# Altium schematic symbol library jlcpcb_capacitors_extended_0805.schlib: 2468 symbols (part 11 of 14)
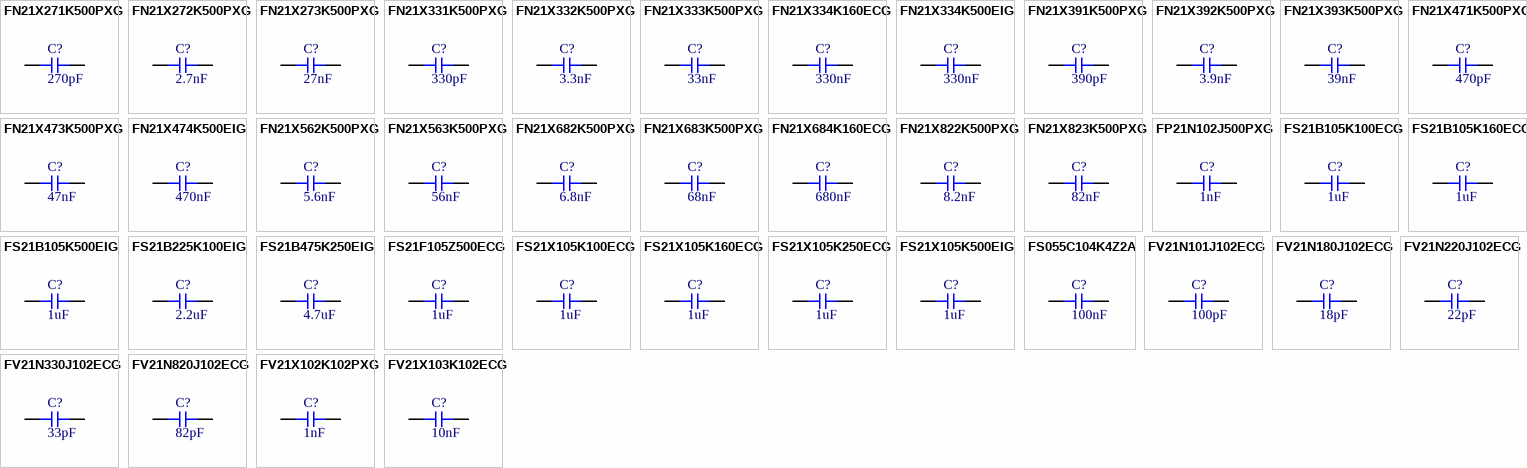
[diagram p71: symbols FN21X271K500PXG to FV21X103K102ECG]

## FS21X105K100ECG
designator C?  Capacitance: 1uF  (hidden comment: *)
Capacitor, Ceramic (MLCC), 1uF, ±10%, 10V, X7R, ±10%, SMD 0805; Manufacturer: PSA(Prosperity Dielectrics); Manufacturer Part Number: FS21X105K100ECG
footprint CAP-0805 (0805 (2012M) Capacitor)
pins: 1, 2

## FS21X105K160ECG
designator C?  Capacitance: 1uF  (hidden comment: *)
Capacitor, Ceramic (MLCC), 1uF, ±10%, 16V, X7R, ±10%, SMD 0805; Manufacturer: PSA(Prosperity Dielectrics); Manufacturer Part Number: FS21X105K160ECG
footprint CAP-0805 (0805 (2012M) Capacitor)
pins: 1, 2

## FS21X105K250ECG
designator C?  Capacitance: 1uF  (hidden comment: *)
Capacitor, Ceramic (MLCC), 1uF, ±10%, 25V, X7R, ±10%, SMD 0805; Manufacturer: PSA(Prosperity Dielectrics); Manufacturer Part Number: FS21X105K250ECG
footprint CAP-0805 (0805 (2012M) Capacitor)
pins: 1, 2

## FS21X105K500EIG
designator C?  Capacitance: 1uF  (hidden comment: *)
Capacitor, Ceramic (MLCC), 1uF, ±10%, 50V, X7R, ±10%, SMD 0805; Manufacturer: PSA(Prosperity Dielectrics); Manufacturer Part Number: FS21X105K500EIG
footprint CAP-0805 (0805 (2012M) Capacitor)
pins: 1, 2

## FS055C104K4Z2A
designator C?  Capacitance: 100nF  (hidden comment: *)
Capacitor, Ceramic (MLCC), 100nF, ±10%, 50V, X7R, ±10%, SMD 0805; Manufacturer: AVX; Manufacturer Part Number: FS055C104K4Z2A
footprint CAP-0805 (0805 (2012M) Capacitor)
pins: 1, 2

## FV21N101J102ECG
designator C?  Capacitance: 100pF  (hidden comment: *)
Capacitor, Ceramic (MLCC), 100pF, ±5%, 1kV, C0G, ±5%, SMD 0805; Manufacturer: PSA(Prosperity Dielectrics); Manufacturer Part Number: FV21N101J102ECG
footprint CAP-0805 (0805 (2012M) Capacitor)
pins: 1, 2

## FV21N180J102ECG
designator C?  Capacitance: 18pF  (hidden comment: *)
Capacitor, Ceramic (MLCC), 18pF, ±5%, 1kV, C0G, ±5%, SMD 0805; Manufacturer: PSA(Prosperity Dielectrics); Manufacturer Part Number: FV21N180J102ECG
footprint CAP-0805 (0805 (2012M) Capacitor)
pins: 1, 2

## FV21N220J102ECG
designator C?  Capacitance: 22pF  (hidden comment: *)
Capacitor, Ceramic (MLCC), 22pF, ±5%, 1kV, NP0, ±5%, SMD 0805; Manufacturer: PSA(Prosperity Dielectrics); Manufacturer Part Number: FV21N220J102ECG
footprint CAP-0805 (0805 (2012M) Capacitor)
pins: 1, 2

## FV21N330J102ECG
designator C?  Capacitance: 33pF  (hidden comment: *)
Capacitor, Ceramic (MLCC), 33pF, ±5%, 1kV, C0G, ±5%, SMD 0805; Manufacturer: PSA(Prosperity Dielectrics); Manufacturer Part Number: FV21N330J102ECG
footprint CAP-0805 (0805 (2012M) Capacitor)
pins: 1, 2

## FV21N820J102ECG
designator C?  Capacitance: 82pF  (hidden comment: *)
Capacitor, Ceramic (MLCC), 82pF, ±5%, 1kV, C0G, ±5%, SMD 0805; Manufacturer: PSA(Prosperity Dielectrics); Manufacturer Part Number: FV21N820J102ECG
footprint CAP-0805 (0805 (2012M) Capacitor)
pins: 1, 2

## FV21X102K102PXG
designator C?  Capacitance: 1nF  (hidden comment: *)
Capacitor, Ceramic (MLCC), 1nF, ±10%, 1kV, X7R, ±10%, SMD 0805; Manufacturer: PSA(Prosperity Dielectrics); Manufacturer Part Number: FV21X102K102PXG
footprint CAP-0805 (0805 (2012M) Capacitor)
pins: 1, 2

## FV21X103K102ECG
designator C?  Capacitance: 10nF  (hidden comment: *)
Capacitor, Ceramic (MLCC), 10nF, ±10%, 1kV, X7R, ±10%, SMD 0805; Manufacturer: PSA(Prosperity Dielectrics); Manufacturer Part Number: FV21X103K102ECG
footprint CAP-0805 (0805 (2012M) Capacitor)
pins: 1, 2

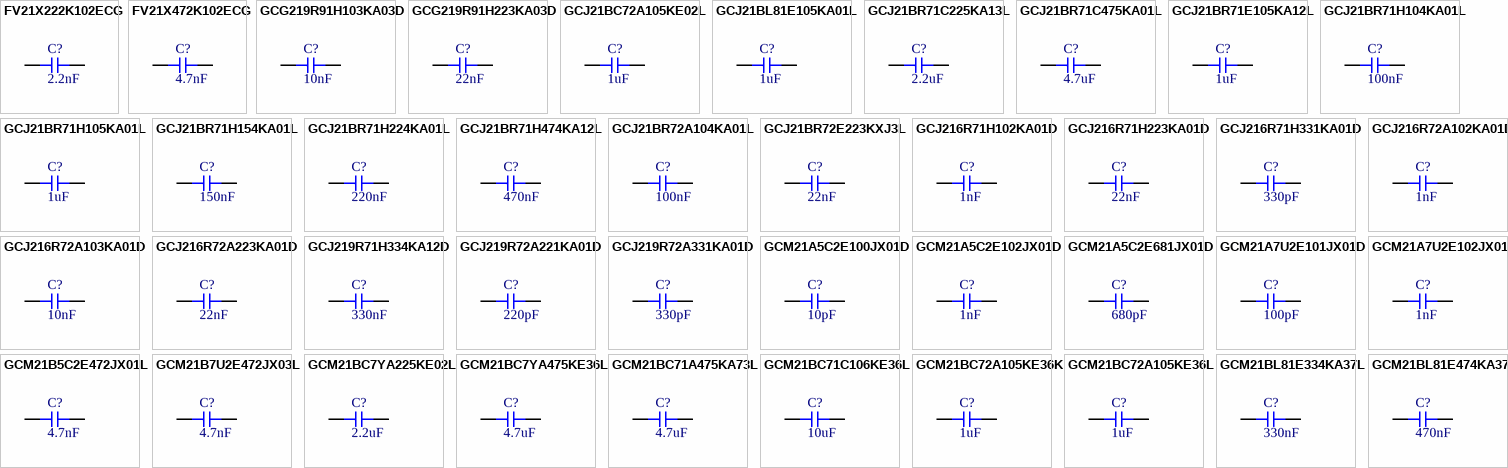
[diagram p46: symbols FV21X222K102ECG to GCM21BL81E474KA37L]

## FV21X222K102ECG
designator C?  Capacitance: 2.2nF  (hidden comment: *)
Capacitor, Ceramic (MLCC), 2.2nF, ±10%, 1kV, X7R, ±10%, SMD 0805; Manufacturer: PSA(Prosperity Dielectrics); Manufacturer Part Number: FV21X222K102ECG
footprint CAP-0805 (0805 (2012M) Capacitor)
pins: 1, 2

## FV21X472K102ECG
designator C?  Capacitance: 4.7nF  (hidden comment: *)
Capacitor, Ceramic (MLCC), 4.7nF, ±10%, 1kV, X7R, ±10%, SMD 0805; Manufacturer: PSA(Prosperity Dielectrics); Manufacturer Part Number: FV21X472K102ECG
footprint CAP-0805 (0805 (2012M) Capacitor)
pins: 1, 2

## GCG219R91H103KA03D
designator C?  Capacitance: 10nF  (hidden comment: *)
Capacitor, Ceramic (MLCC), 10nF, ±10%, 50V, X8R, ±10%, SMD 0805; Manufacturer: Murata Electronics; Manufacturer Part Number: GCG219R91H103KA03D
footprint CAP-0805 (0805 (2012M) Capacitor)
pins: 1, 2

## GCG219R91H223KA03D
designator C?  Capacitance: 22nF  (hidden comment: *)
Capacitor, Ceramic (MLCC), 22nF, ±10%, 50V, X8R, ±10%, SMD 0805; Manufacturer: Murata Electronics; Manufacturer Part Number: GCG219R91H223KA03D
footprint CAP-0805 (0805 (2012M) Capacitor)
pins: 1, 2

## GCJ21BC72A105KE02L
designator C?  Capacitance: 1uF  (hidden comment: *)
Capacitor, Ceramic (MLCC), 1uF, ±10%, 100V, X7S, ±10%, SMD 0805; Manufacturer: Murata Electronics; Manufacturer Part Number: GCJ21BC72A105KE02L
footprint CAP-0805 (0805 (2012M) Capacitor)
pins: 1, 2

## GCJ21BL81E105KA01L
designator C?  Capacitance: 1uF  (hidden comment: *)
Capacitor, Ceramic (MLCC), 1uF, ±10%, 25V, ±10%, SMD 0805; Manufacturer: Murata Electronics; Manufacturer Part Number: GCJ21BL81E105KA01L
footprint CAP-0805 (0805 (2012M) Capacitor)
pins: 1, 2

## GCJ21BR71C225KA13L
designator C?  Capacitance: 2.2uF  (hidden comment: *)
Capacitor, Ceramic (MLCC), 2.2uF, ±10%, 16V, X7R, ±10%, SMD 0805; Manufacturer: Murata Electronics; Manufacturer Part Number: GCJ21BR71C225KA13L
footprint CAP-0805 (0805 (2012M) Capacitor)
pins: 1, 2

## GCJ21BR71C475KA01L
designator C?  Capacitance: 4.7uF  (hidden comment: *)
Capacitor, Ceramic (MLCC), 4.7uF, ±10%, 16V, X7R, ±10%, SMD 0805; Manufacturer: Murata Electronics; Manufacturer Part Number: GCJ21BR71C475KA01L
footprint CAP-0805 (0805 (2012M) Capacitor)
pins: 1, 2

## GCJ21BR71E105KA12L
designator C?  Capacitance: 1uF  (hidden comment: *)
Capacitor, Ceramic (MLCC), 1uF, ±10%, 25V, X7R, ±10%, SMD 0805; Manufacturer: Murata Electronics; Manufacturer Part Number: GCJ21BR71E105KA12L
footprint CAP-0805 (0805 (2012M) Capacitor)
pins: 1, 2

## GCJ21BR71H104KA01L
designator C?  Capacitance: 100nF  (hidden comment: *)
Capacitor, Ceramic (MLCC), 100nF, ±10%, 50V, X7R, ±10%, SMD 0805; Manufacturer: Murata Electronics; Manufacturer Part Number: GCJ21BR71H104KA01L
footprint CAP-0805 (0805 (2012M) Capacitor)
pins: 1, 2

## GCJ21BR71H105KA01L
designator C?  Capacitance: 1uF  (hidden comment: *)
Capacitor, Ceramic (MLCC), 1uF, ±10%, 50V, X7R, ±10%, SMD 0805; Manufacturer: Murata Electronics; Manufacturer Part Number: GCJ21BR71H105KA01L
footprint CAP-0805 (0805 (2012M) Capacitor)
pins: 1, 2

## GCJ21BR71H154KA01L
designator C?  Capacitance: 150nF  (hidden comment: *)
Capacitor, Ceramic (MLCC), 150nF, ±10%, 50V, X7R, ±10%, SMD 0805; Manufacturer: Murata Electronics; Manufacturer Part Number: GCJ21BR71H154KA01L
footprint CAP-0805 (0805 (2012M) Capacitor)
pins: 1, 2

## GCJ21BR71H224KA01L
designator C?  Capacitance: 220nF  (hidden comment: *)
Capacitor, Ceramic (MLCC), 220nF, ±10%, 50V, X7R, ±10%, SMD 0805; Manufacturer: Murata Electronics; Manufacturer Part Number: GCJ21BR71H224KA01L
footprint CAP-0805 (0805 (2012M) Capacitor)
pins: 1, 2

## GCJ21BR71H474KA12L
designator C?  Capacitance: 470nF  (hidden comment: *)
Capacitor, Ceramic (MLCC), 470nF, ±10%, 50V, X7R, ±10%, SMD 0805; Manufacturer: Murata Electronics; Manufacturer Part Number: GCJ21BR71H474KA12L
footprint CAP-0805 (0805 (2012M) Capacitor)
pins: 1, 2

## GCJ21BR72A104KA01L
designator C?  Capacitance: 100nF  (hidden comment: *)
Capacitor, Ceramic (MLCC), 100nF, ±10%, 100V, X7R, ±10%, SMD 0805; Manufacturer: Murata Electronics; Manufacturer Part Number: GCJ21BR72A104KA01L
footprint CAP-0805 (0805 (2012M) Capacitor)
pins: 1, 2

## GCJ21BR72E223KXJ3L
designator C?  Capacitance: 22nF  (hidden comment: *)
Capacitor, Ceramic (MLCC), 22nF, ±10%, 250V, X7R, ±10%, SMD 0805; Manufacturer: Murata Electronics; Manufacturer Part Number: GCJ21BR72E223KXJ3L
footprint CAP-0805 (0805 (2012M) Capacitor)
pins: 1, 2

## GCJ216R71H102KA01D
designator C?  Capacitance: 1nF  (hidden comment: *)
Capacitor, Ceramic (MLCC), 1nF, ±10%, 50V, X7R, ±10%, SMD 0805; Manufacturer: Murata Electronics; Manufacturer Part Number: GCJ216R71H102KA01D
footprint CAP-0805 (0805 (2012M) Capacitor)
pins: 1, 2

## GCJ216R71H223KA01D
designator C?  Capacitance: 22nF  (hidden comment: *)
Capacitor, Ceramic (MLCC), 22nF, ±10%, 50V, X7R, ±10%, SMD 0805; Manufacturer: Murata Electronics; Manufacturer Part Number: GCJ216R71H223KA01D
footprint CAP-0805 (0805 (2012M) Capacitor)
pins: 1, 2

## GCJ216R71H331KA01D
designator C?  Capacitance: 330pF  (hidden comment: *)
Capacitor, Ceramic (MLCC), 330pF, ±10%, 50V, X7R, ±10%, SMD 0805; Manufacturer: Murata Electronics; Manufacturer Part Number: GCJ216R71H331KA01D
footprint CAP-0805 (0805 (2012M) Capacitor)
pins: 1, 2

## GCJ216R72A102KA01D
designator C?  Capacitance: 1nF  (hidden comment: *)
Capacitor, Ceramic (MLCC), 1nF, ±10%, 100V, X7R, ±10%, SMD 0805; Manufacturer: Murata Electronics; Manufacturer Part Number: GCJ216R72A102KA01D
footprint CAP-0805 (0805 (2012M) Capacitor)
pins: 1, 2

## GCJ216R72A103KA01D
designator C?  Capacitance: 10nF  (hidden comment: *)
Capacitor, Ceramic (MLCC), 10nF, ±10%, 100V, X7R, ±10%, SMD 0805; Manufacturer: Murata Electronics; Manufacturer Part Number: GCJ216R72A103KA01D
footprint CAP-0805 (0805 (2012M) Capacitor)
pins: 1, 2

## GCJ216R72A223KA01D
designator C?  Capacitance: 22nF  (hidden comment: *)
Capacitor, Ceramic (MLCC), 22nF, ±10%, 100V, X7R, ±10%, SMD 0805; Manufacturer: Murata Electronics; Manufacturer Part Number: GCJ216R72A223KA01D
footprint CAP-0805 (0805 (2012M) Capacitor)
pins: 1, 2

## GCJ219R71H334KA12D
designator C?  Capacitance: 330nF  (hidden comment: *)
Capacitor, Ceramic (MLCC), 330nF, ±10%, 50V, X7R, ±10%, SMD 0805; Manufacturer: Murata Electronics; Manufacturer Part Number: GCJ219R71H334KA12D
footprint CAP-0805 (0805 (2012M) Capacitor)
pins: 1, 2

## GCJ219R72A221KA01D
designator C?  Capacitance: 220pF  (hidden comment: *)
Capacitor, Ceramic (MLCC), 220pF, ±10%, 100V, X7R, ±10%, SMD 0805; Manufacturer: Murata Electronics; Manufacturer Part Number: GCJ219R72A221KA01D
footprint CAP-0805 (0805 (2012M) Capacitor)
pins: 1, 2

## GCJ219R72A331KA01D
designator C?  Capacitance: 330pF  (hidden comment: *)
Capacitor, Ceramic (MLCC), 330pF, ±10%, 100V, X7R, ±10%, SMD 0805; Manufacturer: Murata Electronics; Manufacturer Part Number: GCJ219R72A331KA01D
footprint CAP-0805 (0805 (2012M) Capacitor)
pins: 1, 2

## GCM21A5C2E100JX01D
designator C?  Capacitance: 10pF  (hidden comment: *)
Capacitor, Ceramic (MLCC), 10pF, ±5%, 250V, C0G, ±5%, SMD 0805; Manufacturer: Murata Electronics; Manufacturer Part Number: GCM21A5C2E100JX01D
footprint CAP-0805 (0805 (2012M) Capacitor)
pins: 1, 2

## GCM21A5C2E102JX01D
designator C?  Capacitance: 1nF  (hidden comment: *)
Capacitor, Ceramic (MLCC), 1nF, ±5%, 250V, C0G, ±5%, SMD 0805; Manufacturer: Murata Electronics; Manufacturer Part Number: GCM21A5C2E102JX01D
footprint CAP-0805 (0805 (2012M) Capacitor)
pins: 1, 2

## GCM21A5C2E681JX01D
designator C?  Capacitance: 680pF  (hidden comment: *)
Capacitor, Ceramic (MLCC), 680pF, ±5%, ±5%, SMD 0805; Manufacturer: Murata Electronics; Manufacturer Part Number: GCM21A5C2E681JX01D
footprint CAP-0805 (0805 (2012M) Capacitor)
pins: 1, 2

## GCM21A7U2E101JX01D
designator C?  Capacitance: 100pF  (hidden comment: *)
Capacitor, Ceramic (MLCC), 100pF, ±5%, ±5%, SMD 0805; Manufacturer: Murata Electronics; Manufacturer Part Number: GCM21A7U2E101JX01D
footprint CAP-0805 (0805 (2012M) Capacitor)
pins: 1, 2

## GCM21A7U2E102JX01D
designator C?  Capacitance: 1nF  (hidden comment: *)
Capacitor, Ceramic (MLCC), 1nF, ±5%, 250V, U2J, ±5%, SMD 0805; Manufacturer: Murata Electronics; Manufacturer Part Number: GCM21A7U2E102JX01D
footprint CAP-0805 (0805 (2012M) Capacitor)
pins: 1, 2

## GCM21B5C2E472JX01L
designator C?  Capacitance: 4.7nF  (hidden comment: *)
Capacitor, Ceramic (MLCC), 4.7nF, ±5%, 250V, C0G, ±5%, SMD 0805; Manufacturer: Murata Electronics; Manufacturer Part Number: GCM21B5C2E472JX01L
footprint CAP-0805 (0805 (2012M) Capacitor)
pins: 1, 2

## GCM21B7U2E472JX03L
designator C?  Capacitance: 4.7nF  (hidden comment: *)
Capacitor, Ceramic (MLCC), 4.7nF, ±5%, 250V, U2J, ±5%, SMD 0805; Manufacturer: Murata Electronics; Manufacturer Part Number: GCM21B7U2E472JX03L
footprint CAP-0805 (0805 (2012M) Capacitor)
pins: 1, 2

## GCM21BC7YA225KE02L
designator C?  Capacitance: 2.2uF  (hidden comment: *)
Capacitor, Ceramic (MLCC), 2.2uF, ±10%, 35V, X7S, ±10%, SMD 0805; Manufacturer: Murata Electronics; Manufacturer Part Number: GCM21BC7YA225KE02L
footprint CAP-0805 (0805 (2012M) Capacitor)
pins: 1, 2

## GCM21BC7YA475KE36L
designator C?  Capacitance: 4.7uF  (hidden comment: *)
Capacitor, Ceramic (MLCC), 4.7uF, ±10%, 35V, X7S, ±10%, SMD 0805; Manufacturer: Murata Electronics; Manufacturer Part Number: GCM21BC7YA475KE36L
footprint CAP-0805 (0805 (2012M) Capacitor)
pins: 1, 2

## GCM21BC71A475KA73L
designator C?  Capacitance: 4.7uF  (hidden comment: *)
Capacitor, Ceramic (MLCC), 4.7uF, ±10%, 10V, X7S, ±10%, SMD 0805; Manufacturer: Murata Electronics; Manufacturer Part Number: GCM21BC71A475KA73L
footprint CAP-0805 (0805 (2012M) Capacitor)
pins: 1, 2

## GCM21BC71C106KE36L
designator C?  Capacitance: 10uF  (hidden comment: *)
Capacitor, Ceramic (MLCC), 10uF, ±10%, 16V, X7S, ±10%, SMD 0805; Manufacturer: Murata Electronics; Manufacturer Part Number: GCM21BC71C106KE36L
footprint CAP-0805 (0805 (2012M) Capacitor)
pins: 1, 2

## GCM21BC72A105KE36K
designator C?  Capacitance: 1uF  (hidden comment: *)
Capacitor, Ceramic (MLCC), 1uF, ±10%, 100V, X7S, ±10%, SMD 0805; Manufacturer: Murata Electronics; Manufacturer Part Number: GCM21BC72A105KE36K
footprint CAP-0805 (0805 (2012M) Capacitor)
pins: 1, 2

## GCM21BC72A105KE36L
designator C?  Capacitance: 1uF  (hidden comment: *)
Capacitor, Ceramic (MLCC), 1uF, ±10%, 100V, X7S, ±10%, SMD 0805; Manufacturer: Murata Electronics; Manufacturer Part Number: GCM21BC72A105KE36L
footprint CAP-0805 (0805 (2012M) Capacitor)
pins: 1, 2

## GCM21BL81E334KA37L
designator C?  Capacitance: 330nF  (hidden comment: *)
Capacitor, Ceramic (MLCC), 330nF, ±10%, 25V, X8L, ±10%, SMD 0805; Manufacturer: Murata Electronics; Manufacturer Part Number: GCM21BL81E334KA37L
footprint CAP-0805 (0805 (2012M) Capacitor)
pins: 1, 2

## GCM21BL81E474KA37L
designator C?  Capacitance: 470nF  (hidden comment: *)
Capacitor, Ceramic (MLCC), 470nF, ±10%, 25V, X8L, ±10%, SMD 0805; Manufacturer: Murata Electronics; Manufacturer Part Number: GCM21BL81E474KA37L
footprint CAP-0805 (0805 (2012M) Capacitor)
pins: 1, 2

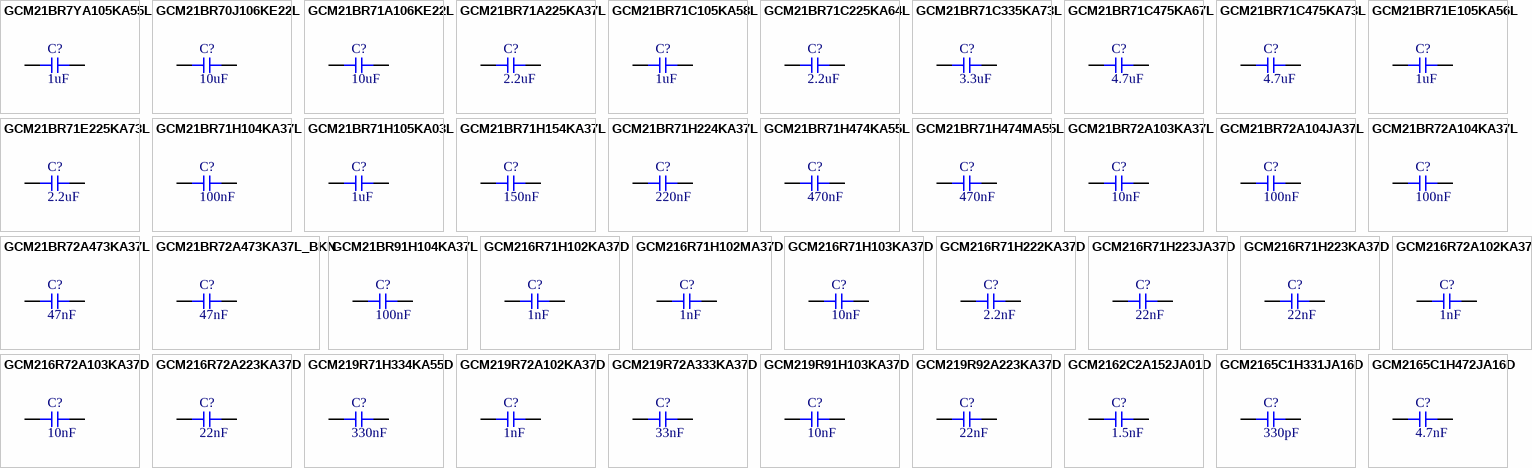
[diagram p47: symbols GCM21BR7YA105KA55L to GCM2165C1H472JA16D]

## GCM21BR7YA105KA55L
designator C?  Capacitance: 1uF  (hidden comment: *)
Capacitor, Ceramic (MLCC), 1uF, ±10%, 35V, X7R, ±10%, SMD 0805; Manufacturer: Murata Electronics; Manufacturer Part Number: GCM21BR7YA105KA55L
footprint CAP-0805 (0805 (2012M) Capacitor)
pins: 1, 2

## GCM21BR70J106KE22L
designator C?  Capacitance: 10uF  (hidden comment: *)
Capacitor, Ceramic (MLCC), 10uF, ±10%, 6.3V, X7R, ±10%, SMD 0805; Manufacturer: Murata Electronics; Manufacturer Part Number: GCM21BR70J106KE22L
footprint CAP-0805 (0805 (2012M) Capacitor)
pins: 1, 2

## GCM21BR71A106KE22L
designator C?  Capacitance: 10uF  (hidden comment: *)
Capacitor, Ceramic (MLCC), 10uF, ±10%, 10V, X7R, ±10%, SMD 0805; Manufacturer: Murata Electronics; Manufacturer Part Number: GCM21BR71A106KE22L
footprint CAP-0805 (0805 (2012M) Capacitor)
pins: 1, 2

## GCM21BR71A225KA37L
designator C?  Capacitance: 2.2uF  (hidden comment: *)
Capacitor, Ceramic (MLCC), 2.2uF, ±10%, 10V, X7R, ±10%, SMD 0805; Manufacturer: Murata Electronics; Manufacturer Part Number: GCM21BR71A225KA37L
footprint CAP-0805 (0805 (2012M) Capacitor)
pins: 1, 2

## GCM21BR71C105KA58L
designator C?  Capacitance: 1uF  (hidden comment: *)
Capacitor, Ceramic (MLCC), 1uF, ±10%, 16V, X7R, ±10%, SMD 0805; Manufacturer: Murata Electronics; Manufacturer Part Number: GCM21BR71C105KA58L
footprint CAP-0805 (0805 (2012M) Capacitor)
pins: 1, 2

## GCM21BR71C225KA64L
designator C?  Capacitance: 2.2uF  (hidden comment: *)
Capacitor, Ceramic (MLCC), 2.2uF, ±10%, 16V, X7R, ±10%, SMD 0805; Manufacturer: Murata Electronics; Manufacturer Part Number: GCM21BR71C225KA64L
footprint CAP-0805 (0805 (2012M) Capacitor)
pins: 1, 2

## GCM21BR71C335KA73L
designator C?  Capacitance: 3.3uF  (hidden comment: *)
Capacitor, Ceramic (MLCC), 3.3uF, ±10%, 16V, X7R, ±10%, SMD 0805; Manufacturer: Murata Electronics; Manufacturer Part Number: GCM21BR71C335KA73L
footprint CAP-0805 (0805 (2012M) Capacitor)
pins: 1, 2

## GCM21BR71C475KA67L
designator C?  Capacitance: 4.7uF  (hidden comment: *)
Capacitor, Ceramic (MLCC), 4.7uF, ±10%, 16V, X7R, ±10%, SMD 0805; Manufacturer: Murata Electronics; Manufacturer Part Number: GCM21BR71C475KA67L
footprint CAP-0805 (0805 (2012M) Capacitor)
pins: 1, 2

## GCM21BR71C475KA73L
designator C?  Capacitance: 4.7uF  (hidden comment: *)
Capacitor, Ceramic (MLCC), 4.7uF, ±10%, 16V, X7R, ±10%, SMD 0805; Manufacturer: Murata Electronics; Manufacturer Part Number: GCM21BR71C475KA73L
footprint CAP-0805 (0805 (2012M) Capacitor)
pins: 1, 2

## GCM21BR71E105KA56L
designator C?  Capacitance: 1uF  (hidden comment: *)
Capacitor, Ceramic (MLCC), 1uF, ±10%, 25V, X7R, ±10%, SMD 0805; Manufacturer: Murata Electronics; Manufacturer Part Number: GCM21BR71E105KA56L
footprint CAP-0805 (0805 (2012M) Capacitor)
pins: 1, 2

## GCM21BR71E225KA73L
designator C?  Capacitance: 2.2uF  (hidden comment: *)
Capacitor, Ceramic (MLCC), 2.2uF, ±10%, 25V, X7R, ±10%, SMD 0805; Manufacturer: Murata Electronics; Manufacturer Part Number: GCM21BR71E225KA73L
footprint CAP-0805 (0805 (2012M) Capacitor)
pins: 1, 2

## GCM21BR71H104KA37L
designator C?  Capacitance: 100nF  (hidden comment: *)
Capacitor, Ceramic (MLCC), 100nF, ±10%, 50V, X7R, ±10%, SMD 0805; Manufacturer: Murata Electronics; Manufacturer Part Number: GCM21BR71H104KA37L
footprint CAP-0805 (0805 (2012M) Capacitor)
pins: 1, 2

## GCM21BR71H105KA03L
designator C?  Capacitance: 1uF  (hidden comment: *)
Capacitor, Ceramic (MLCC), 1uF, ±10%, 50V, X7R, ±10%, SMD 0805; Manufacturer: Murata Electronics; Manufacturer Part Number: GCM21BR71H105KA03L
footprint CAP-0805 (0805 (2012M) Capacitor)
pins: 1, 2

## GCM21BR71H154KA37L
designator C?  Capacitance: 150nF  (hidden comment: *)
Capacitor, Ceramic (MLCC), 150nF, ±10%, 50V, X7R, ±10%, SMD 0805; Manufacturer: Murata Electronics; Manufacturer Part Number: GCM21BR71H154KA37L
footprint CAP-0805 (0805 (2012M) Capacitor)
pins: 1, 2

## GCM21BR71H224KA37L
designator C?  Capacitance: 220nF  (hidden comment: *)
Capacitor, Ceramic (MLCC), 220nF, ±10%, 50V, X7R, ±10%, SMD 0805; Manufacturer: Murata Electronics; Manufacturer Part Number: GCM21BR71H224KA37L
footprint CAP-0805 (0805 (2012M) Capacitor)
pins: 1, 2

## GCM21BR71H474KA55L
designator C?  Capacitance: 470nF  (hidden comment: *)
Capacitor, Ceramic (MLCC), 470nF, ±10%, 50V, X7R, ±10%, SMD 0805; Manufacturer: Murata Electronics; Manufacturer Part Number: GCM21BR71H474KA55L
footprint CAP-0805 (0805 (2012M) Capacitor)
pins: 1, 2

## GCM21BR71H474MA55L
designator C?  Capacitance: 470nF  (hidden comment: *)
Capacitor, Ceramic (MLCC), 470nF, ±20%, 50V, X7R, ±20%, SMD 0805; Manufacturer: Murata Electronics; Manufacturer Part Number: GCM21BR71H474MA55L
footprint CAP-0805 (0805 (2012M) Capacitor)
pins: 1, 2

## GCM21BR72A103KA37L
designator C?  Capacitance: 10nF  (hidden comment: *)
Capacitor, Ceramic (MLCC), 10nF, ±10%, 100V, X7R, ±10%, SMD 0805; Manufacturer: Murata Electronics; Manufacturer Part Number: GCM21BR72A103KA37L
footprint CAP-0805 (0805 (2012M) Capacitor)
pins: 1, 2

## GCM21BR72A104JA37L
designator C?  Capacitance: 100nF  (hidden comment: *)
Capacitor, Ceramic (MLCC), 100nF, ±5%, 100V, X7R, ±5%, SMD 0805; Manufacturer: Murata Electronics; Manufacturer Part Number: GCM21BR72A104JA37L
footprint CAP-0805 (0805 (2012M) Capacitor)
pins: 1, 2

## GCM21BR72A104KA37L
designator C?  Capacitance: 100nF  (hidden comment: *)
Capacitor, Ceramic (MLCC), 100nF, ±10%, 100V, X7R, ±10%, SMD 0805; Manufacturer: Murata Electronics; Manufacturer Part Number: GCM21BR72A104KA37L
footprint CAP-0805 (0805 (2012M) Capacitor)
pins: 1, 2

## GCM21BR72A473KA37L
designator C?  Capacitance: 47nF  (hidden comment: *)
Capacitor, Ceramic (MLCC), 47nF, ±10%, 100V, X7R, ±10%, SMD 0805; Manufacturer: Murata Electronics; Manufacturer Part Number: GCM21BR72A473KA37L
footprint CAP-0805 (0805 (2012M) Capacitor)
pins: 1, 2

## GCM21BR72A473KA37L_BKN
designator C?  Capacitance: 47nF  (hidden comment: *)
Capacitor, Ceramic (MLCC), 47nF, ±10%, 100V, X7R, ±10%, SMD 0805; Manufacturer: Murata Electronics; Manufacturer Part Number: GCM21BR72A473KA37L/BKN
footprint CAP-0805 (0805 (2012M) Capacitor)
pins: 1, 2

## GCM21BR91H104KA37L
designator C?  Capacitance: 100nF  (hidden comment: *)
Capacitor, Ceramic (MLCC), 100nF, ±10%, 50V, X8R, ±10%, SMD 0805; Manufacturer: Murata Electronics; Manufacturer Part Number: GCM21BR91H104KA37L
footprint CAP-0805 (0805 (2012M) Capacitor)
pins: 1, 2

## GCM216R71H102KA37D
designator C?  Capacitance: 1nF  (hidden comment: *)
Capacitor, Ceramic (MLCC), 1nF, ±10%, 50V, X7R, ±10%, SMD 0805; Manufacturer: Murata Electronics; Manufacturer Part Number: GCM216R71H102KA37D
footprint CAP-0805 (0805 (2012M) Capacitor)
pins: 1, 2

## GCM216R71H102MA37D
designator C?  Capacitance: 1nF  (hidden comment: *)
Capacitor, Ceramic (MLCC), 1nF, ±20%, 50V, X7R, ±20%, SMD 0805; Manufacturer: Murata Electronics; Manufacturer Part Number: GCM216R71H102MA37D
footprint CAP-0805 (0805 (2012M) Capacitor)
pins: 1, 2

## GCM216R71H103KA37D
designator C?  Capacitance: 10nF  (hidden comment: *)
Capacitor, Ceramic (MLCC), 10nF, ±10%, 50V, X7R, ±10%, SMD 0805; Manufacturer: Murata Electronics; Manufacturer Part Number: GCM216R71H103KA37D
footprint CAP-0805 (0805 (2012M) Capacitor)
pins: 1, 2

## GCM216R71H222KA37D
designator C?  Capacitance: 2.2nF  (hidden comment: *)
Capacitor, Ceramic (MLCC), 2.2nF, ±10%, 50V, X7R, ±10%, SMD 0805; Manufacturer: Murata Electronics; Manufacturer Part Number: GCM216R71H222KA37D
footprint CAP-0805 (0805 (2012M) Capacitor)
pins: 1, 2

## GCM216R71H223JA37D
designator C?  Capacitance: 22nF  (hidden comment: *)
Capacitor, Ceramic (MLCC), 22nF, ±5%, 50V, X7R, ±5%, SMD 0805; Manufacturer: Murata Electronics; Manufacturer Part Number: GCM216R71H223JA37D
footprint CAP-0805 (0805 (2012M) Capacitor)
pins: 1, 2

## GCM216R71H223KA37D
designator C?  Capacitance: 22nF  (hidden comment: *)
Capacitor, Ceramic (MLCC), 22nF, ±10%, 50V, X7R, ±10%, SMD 0805; Manufacturer: Murata Electronics; Manufacturer Part Number: GCM216R71H223KA37D
footprint CAP-0805 (0805 (2012M) Capacitor)
pins: 1, 2

## GCM216R72A102KA37D
designator C?  Capacitance: 1nF  (hidden comment: *)
Capacitor, Ceramic (MLCC), 1nF, ±10%, 100V, X7R, ±10%, SMD 0805; Manufacturer: Murata Electronics; Manufacturer Part Number: GCM216R72A102KA37D
footprint CAP-0805 (0805 (2012M) Capacitor)
pins: 1, 2

## GCM216R72A103KA37D
designator C?  Capacitance: 10nF  (hidden comment: *)
Capacitor, Ceramic (MLCC), 10nF, ±10%, 100V, X7R, ±10%, SMD 0805; Manufacturer: Murata Electronics; Manufacturer Part Number: GCM216R72A103KA37D
footprint CAP-0805 (0805 (2012M) Capacitor)
pins: 1, 2

## GCM216R72A223KA37D
designator C?  Capacitance: 22nF  (hidden comment: *)
Capacitor, Ceramic (MLCC), 22nF, ±10%, 100V, X7R, ±10%, SMD 0805; Manufacturer: Murata Electronics; Manufacturer Part Number: GCM216R72A223KA37D
footprint CAP-0805 (0805 (2012M) Capacitor)
pins: 1, 2

## GCM219R71H334KA55D
designator C?  Capacitance: 330nF  (hidden comment: *)
Capacitor, Ceramic (MLCC), 330nF, ±10%, 50V, X7R, ±10%, SMD 0805; Manufacturer: Murata Electronics; Manufacturer Part Number: GCM219R71H334KA55D
footprint CAP-0805 (0805 (2012M) Capacitor)
pins: 1, 2

## GCM219R72A102KA37D
designator C?  Capacitance: 1nF  (hidden comment: *)
Capacitor, Ceramic (MLCC), 1nF, ±10%, 100V, X7R, ±10%, SMD 0805; Manufacturer: Murata Electronics; Manufacturer Part Number: GCM219R72A102KA37D
footprint CAP-0805 (0805 (2012M) Capacitor)
pins: 1, 2

## GCM219R72A333KA37D
designator C?  Capacitance: 33nF  (hidden comment: *)
Capacitor, Ceramic (MLCC), 33nF, ±10%, 100V, X7R, ±10%, SMD 0805; Manufacturer: Murata Electronics; Manufacturer Part Number: GCM219R72A333KA37D
footprint CAP-0805 (0805 (2012M) Capacitor)
pins: 1, 2

## GCM219R91H103KA37D
designator C?  Capacitance: 10nF  (hidden comment: *)
Capacitor, Ceramic (MLCC), 10nF, ±10%, 50V, X8R, ±10%, SMD 0805; Manufacturer: Murata Electronics; Manufacturer Part Number: GCM219R91H103KA37D
footprint CAP-0805 (0805 (2012M) Capacitor)
pins: 1, 2

## GCM219R92A223KA37D
designator C?  Capacitance: 22nF  (hidden comment: *)
Capacitor, Ceramic (MLCC), 22nF, ±10%, 100V, ±10%, SMD 0805; Manufacturer: Murata Electronics; Manufacturer Part Number: GCM219R92A223KA37D
footprint CAP-0805 (0805 (2012M) Capacitor)
pins: 1, 2

## GCM2162C2A152JA01D
designator C?  Capacitance: 1.5nF  (hidden comment: *)
Capacitor, Ceramic (MLCC), 1.5nF, ±5%, 100V, CH, ±5%, SMD 0805; Manufacturer: Murata Electronics; Manufacturer Part Number: GCM2162C2A152JA01D
footprint CAP-0805 (0805 (2012M) Capacitor)
pins: 1, 2

## GCM2165C1H331JA16D
designator C?  Capacitance: 330pF  (hidden comment: *)
Capacitor, Ceramic (MLCC), 330pF, ±5%, 50V, C0G, ±5%, SMD 0805; Manufacturer: Murata Electronics; Manufacturer Part Number: GCM2165C1H331JA16D
footprint CAP-0805 (0805 (2012M) Capacitor)
pins: 1, 2

## GCM2165C1H472JA16D
designator C?  Capacitance: 4.7nF  (hidden comment: *)
Capacitor, Ceramic (MLCC), 4.7nF, ±5%, 50V, C0G, ±5%, SMD 0805; Manufacturer: Murata Electronics; Manufacturer Part Number: GCM2165C1H472JA16D
footprint CAP-0805 (0805 (2012M) Capacitor)
pins: 1, 2

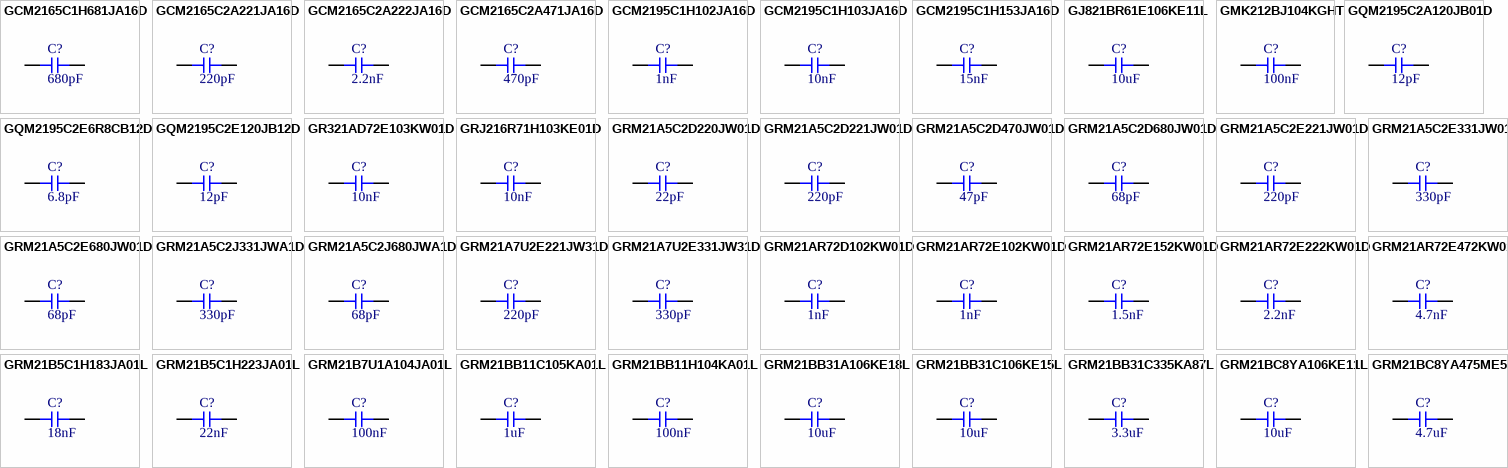
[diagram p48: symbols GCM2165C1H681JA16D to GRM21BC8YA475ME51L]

## GCM2165C1H681JA16D
designator C?  Capacitance: 680pF  (hidden comment: *)
Capacitor, Ceramic (MLCC), 680pF, ±5%, 50V, C0G, ±5%, SMD 0805; Manufacturer: Murata Electronics; Manufacturer Part Number: GCM2165C1H681JA16D
footprint CAP-0805 (0805 (2012M) Capacitor)
pins: 1, 2

## GCM2165C2A221JA16D
designator C?  Capacitance: 220pF  (hidden comment: *)
Capacitor, Ceramic (MLCC), 220pF, ±5%, ±5%, SMD 0805; Manufacturer: Murata Electronics; Manufacturer Part Number: GCM2165C2A221JA16D
footprint CAP-0805 (0805 (2012M) Capacitor)
pins: 1, 2

## GCM2165C2A222JA16D
designator C?  Capacitance: 2.2nF  (hidden comment: *)
Capacitor, Ceramic (MLCC), 2.2nF, ±5%, 100V, C0G, ±5%, SMD 0805; Manufacturer: Murata Electronics; Manufacturer Part Number: GCM2165C2A222JA16D
footprint CAP-0805 (0805 (2012M) Capacitor)
pins: 1, 2

## GCM2165C2A471JA16D
designator C?  Capacitance: 470pF  (hidden comment: *)
Capacitor, Ceramic (MLCC), 470pF, ±5%, 100V, C0G, ±5%, SMD 0805; Manufacturer: Murata Electronics; Manufacturer Part Number: GCM2165C2A471JA16D
footprint CAP-0805 (0805 (2012M) Capacitor)
pins: 1, 2

## GCM2195C1H102JA16D
designator C?  Capacitance: 1nF  (hidden comment: *)
Capacitor, Ceramic (MLCC), 1nF, ±5%, 50V, C0G, ±5%, SMD 0805; Manufacturer: Murata Electronics; Manufacturer Part Number: GCM2195C1H102JA16D
footprint CAP-0805 (0805 (2012M) Capacitor)
pins: 1, 2

## GCM2195C1H103JA16D
designator C?  Capacitance: 10nF  (hidden comment: *)
Capacitor, Ceramic (MLCC), 10nF, ±5%, 50V, C0G, ±5%, SMD 0805; Manufacturer: Murata Electronics; Manufacturer Part Number: GCM2195C1H103JA16D
footprint CAP-0805 (0805 (2012M) Capacitor)
pins: 1, 2

## GCM2195C1H153JA16D
designator C?  Capacitance: 15nF  (hidden comment: *)
Capacitor, Ceramic (MLCC), 15nF, ±5%, 50V, C0G, ±5%, SMD 0805; Manufacturer: Murata Electronics; Manufacturer Part Number: GCM2195C1H153JA16D
footprint CAP-0805 (0805 (2012M) Capacitor)
pins: 1, 2

## GJ821BR61E106KE11L
designator C?  Capacitance: 10uF  (hidden comment: *)
Capacitor, Ceramic (MLCC), 10uF, ±10%, 25V, X5R, ±10%, SMD 0805; Manufacturer: Murata Electronics; Manufacturer Part Number: GJ821BR61E106KE11L
footprint CAP-0805 (0805 (2012M) Capacitor)
pins: 1, 2

## GMK212BJ104KGHT
designator C?  Capacitance: 100nF  (hidden comment: *)
Capacitor, Ceramic (MLCC), 100nF, ±10%, 35V, X5R, ±10%, SMD 0805; Manufacturer: Taiyo Yuden; Manufacturer Part Number: GMK212BJ104KGHT
footprint CAP-0805 (0805 (2012M) Capacitor)
pins: 1, 2

## GQM2195C2A120JB01D
designator C?  Capacitance: 12pF  (hidden comment: *)
Capacitor, Ceramic (MLCC), 12pF, ±5%, 100V, C0G, ±5%, SMD 0805; Manufacturer: Murata Electronics; Manufacturer Part Number: GQM2195C2A120JB01D
footprint CAP-0805 (0805 (2012M) Capacitor)
pins: 1, 2

## GQM2195C2E6R8CB12D
designator C?  Capacitance: 6.8pF  (hidden comment: *)
Capacitor, Ceramic (MLCC), 6.8pF, ±0.25pF, 250V, C0G, ±0.25pF, SMD 0805; Manufacturer: Murata Electronics; Manufacturer Part Number: GQM2195C2E6R8CB12D
footprint CAP-0805 (0805 (2012M) Capacitor)
pins: 1, 2

## GQM2195C2E120JB12D
designator C?  Capacitance: 12pF  (hidden comment: *)
Capacitor, Ceramic (MLCC), 12pF, ±5%, 250V, C0G, ±5%, SMD 0805; Manufacturer: Murata Electronics; Manufacturer Part Number: GQM2195C2E120JB12D
footprint CAP-0805 (0805 (2012M) Capacitor)
pins: 1, 2

## GR321AD72E103KW01D
designator C?  Capacitance: 10nF  (hidden comment: *)
Capacitor, Ceramic (MLCC), 10nF, ±10%, 250V, X7T, ±10%, SMD 0805; Manufacturer: Murata Electronics; Manufacturer Part Number: GR321AD72E103KW01D
footprint CAP-0805 (0805 (2012M) Capacitor)
pins: 1, 2

## GRJ216R71H103KE01D
designator C?  Capacitance: 10nF  (hidden comment: *)
Capacitor, Ceramic (MLCC), 10nF, ±10%, 50V, X7R, ±10%, SMD 0805; Manufacturer: Murata Electronics; Manufacturer Part Number: GRJ216R71H103KE01D
footprint CAP-0805 (0805 (2012M) Capacitor)
pins: 1, 2

## GRM21A5C2D220JW01D
designator C?  Capacitance: 22pF  (hidden comment: *)
Capacitor, Ceramic (MLCC), 22pF, ±5%, 200V, C0G, ±5%, SMD 0805; Manufacturer: Murata Electronics; Manufacturer Part Number: GRM21A5C2D220JW01D
footprint CAP-0805 (0805 (2012M) Capacitor)
pins: 1, 2

## GRM21A5C2D221JW01D
designator C?  Capacitance: 220pF  (hidden comment: *)
Capacitor, Ceramic (MLCC), 220pF, ±5%, 200V, C0G, ±5%, SMD 0805; Manufacturer: Murata Electronics; Manufacturer Part Number: GRM21A5C2D221JW01D
footprint CAP-0805 (0805 (2012M) Capacitor)
pins: 1, 2

## GRM21A5C2D470JW01D
designator C?  Capacitance: 47pF  (hidden comment: *)
Capacitor, Ceramic (MLCC), 47pF, ±5%, 200V, C0G, ±5%, SMD 0805; Manufacturer: Murata Electronics; Manufacturer Part Number: GRM21A5C2D470JW01D
footprint CAP-0805 (0805 (2012M) Capacitor)
pins: 1, 2

## GRM21A5C2D680JW01D
designator C?  Capacitance: 68pF  (hidden comment: *)
Capacitor, Ceramic (MLCC), 68pF, ±5%, 200V, C0G, ±5%, SMD 0805; Manufacturer: Murata Electronics; Manufacturer Part Number: GRM21A5C2D680JW01D
footprint CAP-0805 (0805 (2012M) Capacitor)
pins: 1, 2

## GRM21A5C2E221JW01D
designator C?  Capacitance: 220pF  (hidden comment: *)
Capacitor, Ceramic (MLCC), 220pF, ±5%, 250V, C0G, ±5%, SMD 0805; Manufacturer: Murata Electronics; Manufacturer Part Number: GRM21A5C2E221JW01D
footprint CAP-0805 (0805 (2012M) Capacitor)
pins: 1, 2

## GRM21A5C2E331JW01D
designator C?  Capacitance: 330pF  (hidden comment: *)
Capacitor, Ceramic (MLCC), 330pF, ±5%, 250V, C0G, ±5%, SMD 0805; Manufacturer: Murata Electronics; Manufacturer Part Number: GRM21A5C2E331JW01D
footprint CAP-0805 (0805 (2012M) Capacitor)
pins: 1, 2

## GRM21A5C2E680JW01D
designator C?  Capacitance: 68pF  (hidden comment: *)
Capacitor, Ceramic (MLCC), 68pF, ±5%, 250V, C0G, ±5%, SMD 0805; Manufacturer: Murata Electronics; Manufacturer Part Number: GRM21A5C2E680JW01D
footprint CAP-0805 (0805 (2012M) Capacitor)
pins: 1, 2

## GRM21A5C2J331JWA1D
designator C?  Capacitance: 330pF  (hidden comment: *)
Capacitor, Ceramic (MLCC), 330pF, ±5%, ±5%, SMD 0805; Manufacturer: Murata Electronics; Manufacturer Part Number: GRM21A5C2J331JWA1D
footprint CAP-0805 (0805 (2012M) Capacitor)
pins: 1, 2

## GRM21A5C2J680JWA1D
designator C?  Capacitance: 68pF  (hidden comment: *)
Capacitor, Ceramic (MLCC), 68pF, ±5%, 630V, C0G, ±5%, SMD 0805; Manufacturer: Murata Electronics; Manufacturer Part Number: GRM21A5C2J680JWA1D
footprint CAP-0805 (0805 (2012M) Capacitor)
pins: 1, 2

## GRM21A7U2E221JW31D
designator C?  Capacitance: 220pF  (hidden comment: *)
Capacitor, Ceramic (MLCC), 220pF, ±5%, 250V, U2J, ±5%, SMD 0805; Manufacturer: Murata Electronics; Manufacturer Part Number: GRM21A7U2E221JW31D
footprint CAP-0805 (0805 (2012M) Capacitor)
pins: 1, 2

## GRM21A7U2E331JW31D
designator C?  Capacitance: 330pF  (hidden comment: *)
Capacitor, Ceramic (MLCC), 330pF, ±5%, 250V, U2J, ±5%, SMD 0805; Manufacturer: Murata Electronics; Manufacturer Part Number: GRM21A7U2E331JW31D
footprint CAP-0805 (0805 (2012M) Capacitor)
pins: 1, 2

## GRM21AR72D102KW01D
designator C?  Capacitance: 1nF  (hidden comment: *)
Capacitor, Ceramic (MLCC), 1nF, ±10%, 200V, X7R, ±10%, SMD 0805; Manufacturer: Murata Electronics; Manufacturer Part Number: GRM21AR72D102KW01D
footprint CAP-0805 (0805 (2012M) Capacitor)
pins: 1, 2

## GRM21AR72E102KW01D
designator C?  Capacitance: 1nF  (hidden comment: *)
Capacitor, Ceramic (MLCC), 1nF, ±10%, 250V, X7R, ±10%, SMD 0805; Manufacturer: Murata Electronics; Manufacturer Part Number: GRM21AR72E102KW01D
footprint CAP-0805 (0805 (2012M) Capacitor)
pins: 1, 2

## GRM21AR72E152KW01D
designator C?  Capacitance: 1.5nF  (hidden comment: *)
Capacitor, Ceramic (MLCC), 1.5nF, ±10%, 250V, X7R, ±10%, SMD 0805; Manufacturer: Murata Electronics; Manufacturer Part Number: GRM21AR72E152KW01D
footprint CAP-0805 (0805 (2012M) Capacitor)
pins: 1, 2

## GRM21AR72E222KW01D
designator C?  Capacitance: 2.2nF  (hidden comment: *)
Capacitor, Ceramic (MLCC), 2.2nF, ±10%, 250V, X7R, ±10%, SMD 0805; Manufacturer: Murata Electronics; Manufacturer Part Number: GRM21AR72E222KW01D
footprint CAP-0805 (0805 (2012M) Capacitor)
pins: 1, 2

## GRM21AR72E472KW01D
designator C?  Capacitance: 4.7nF  (hidden comment: *)
Capacitor, Ceramic (MLCC), 4.7nF, ±10%, 250V, X7R, ±10%, SMD 0805; Manufacturer: Murata Electronics; Manufacturer Part Number: GRM21AR72E472KW01D
footprint CAP-0805 (0805 (2012M) Capacitor)
pins: 1, 2

## GRM21B5C1H183JA01L
designator C?  Capacitance: 18nF  (hidden comment: *)
Capacitor, Ceramic (MLCC), 18nF, ±5%, 50V, C0G, ±5%, SMD 0805; Manufacturer: Murata Electronics; Manufacturer Part Number: GRM21B5C1H183JA01L
footprint CAP-0805 (0805 (2012M) Capacitor)
pins: 1, 2

## GRM21B5C1H223JA01L
designator C?  Capacitance: 22nF  (hidden comment: *)
Capacitor, Ceramic (MLCC), 22nF, ±5%, 50V, C0G, ±5%, SMD 0805; Manufacturer: Murata Electronics; Manufacturer Part Number: GRM21B5C1H223JA01L
footprint CAP-0805 (0805 (2012M) Capacitor)
pins: 1, 2

## GRM21B7U1A104JA01L
designator C?  Capacitance: 100nF  (hidden comment: *)
Capacitor, Ceramic (MLCC), 100nF, ±5%, ±5%, SMD 0805; Manufacturer: Murata Electronics; Manufacturer Part Number: GRM21B7U1A104JA01L
footprint CAP-0805 (0805 (2012M) Capacitor)
pins: 1, 2

## GRM21BB11C105KA01L
designator C?  Capacitance: 1uF  (hidden comment: *)
Capacitor, Ceramic (MLCC), 1uF, ±10%, 16V, B, ±10%, SMD 0805; Manufacturer: Murata Electronics; Manufacturer Part Number: GRM21BB11C105KA01L
footprint CAP-0805 (0805 (2012M) Capacitor)
pins: 1, 2

## GRM21BB11H104KA01L
designator C?  Capacitance: 100nF  (hidden comment: *)
Capacitor, Ceramic (MLCC), 100nF, ±10%, 50V, B, ±10%, SMD 0805; Manufacturer: Murata Electronics; Manufacturer Part Number: GRM21BB11H104KA01L
footprint CAP-0805 (0805 (2012M) Capacitor)
pins: 1, 2

## GRM21BB31A106KE18L
designator C?  Capacitance: 10uF  (hidden comment: *)
Capacitor, Ceramic (MLCC), 10uF, ±10%, 10V, B, ±10%, SMD 0805; Manufacturer: Murata Electronics; Manufacturer Part Number: GRM21BB31A106KE18L
footprint CAP-0805 (0805 (2012M) Capacitor)
pins: 1, 2

## GRM21BB31C106KE15L
designator C?  Capacitance: 10uF  (hidden comment: *)
Capacitor, Ceramic (MLCC), 10uF, ±10%, 16V, B, ±10%, SMD 0805; Manufacturer: Murata Electronics; Manufacturer Part Number: GRM21BB31C106KE15L
footprint CAP-0805 (0805 (2012M) Capacitor)
pins: 1, 2

## GRM21BB31C335KA87L
designator C?  Capacitance: 3.3uF  (hidden comment: *)
Capacitor, Ceramic (MLCC), 3.3uF, ±10%, 16V, B, ±10%, SMD 0805; Manufacturer: Murata Electronics; Manufacturer Part Number: GRM21BB31C335KA87L
footprint CAP-0805 (0805 (2012M) Capacitor)
pins: 1, 2

## GRM21BC8YA106KE11L
designator C?  Capacitance: 10uF  (hidden comment: *)
Capacitor, Ceramic (MLCC), 10uF, ±10%, 35V, X6S, ±10%, SMD 0805; Manufacturer: Murata Electronics; Manufacturer Part Number: GRM21BC8YA106KE11L
footprint CAP-0805 (0805 (2012M) Capacitor)
pins: 1, 2

## GRM21BC8YA475ME51L
designator C?  Capacitance: 4.7uF  (hidden comment: *)
Capacitor, Ceramic (MLCC), 4.7uF, ±20%, 35V, X6S, ±20%, SMD 0805; Manufacturer: Murata Electronics; Manufacturer Part Number: GRM21BC8YA475ME51L
footprint CAP-0805 (0805 (2012M) Capacitor)
pins: 1, 2

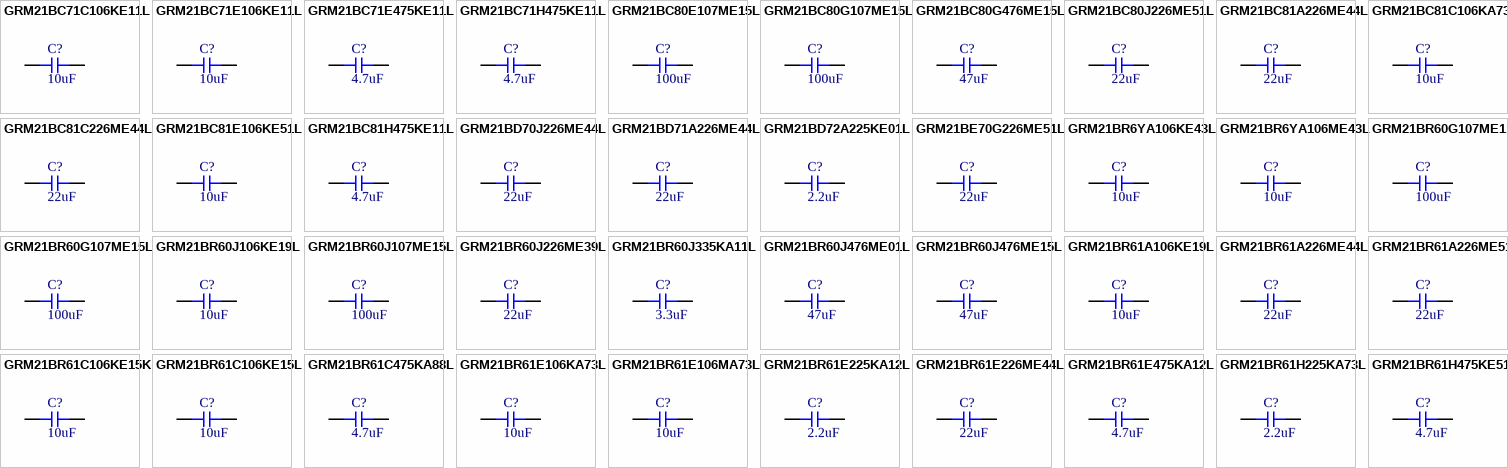
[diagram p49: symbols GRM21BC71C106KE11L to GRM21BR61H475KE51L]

## GRM21BC71C106KE11L
designator C?  Capacitance: 10uF  (hidden comment: *)
Capacitor, Ceramic (MLCC), 10uF, ±10%, 16V, X7S, ±10%, SMD 0805; Manufacturer: Murata Electronics; Manufacturer Part Number: GRM21BC71C106KE11L
footprint CAP-0805 (0805 (2012M) Capacitor)
pins: 1, 2

## GRM21BC71E106KE11L
designator C?  Capacitance: 10uF  (hidden comment: *)
Capacitor, Ceramic (MLCC), 10uF, ±10%, 25V, X7S, ±10%, SMD 0805; Manufacturer: Murata Electronics; Manufacturer Part Number: GRM21BC71E106KE11L
footprint CAP-0805 (0805 (2012M) Capacitor)
pins: 1, 2

## GRM21BC71E475KE11L
designator C?  Capacitance: 4.7uF  (hidden comment: *)
Capacitor, Ceramic (MLCC), 4.7uF, ±10%, 25V, X7S, ±10%, SMD 0805; Manufacturer: Murata Electronics; Manufacturer Part Number: GRM21BC71E475KE11L
footprint CAP-0805 (0805 (2012M) Capacitor)
pins: 1, 2

## GRM21BC71H475KE11L
designator C?  Capacitance: 4.7uF  (hidden comment: *)
Capacitor, Ceramic (MLCC), 4.7uF, ±10%, 50V, X7S, ±10%, SMD 0805; Manufacturer: Murata Electronics; Manufacturer Part Number: GRM21BC71H475KE11L
footprint CAP-0805 (0805 (2012M) Capacitor)
pins: 1, 2

## GRM21BC80E107ME15L
designator C?  Capacitance: 100uF  (hidden comment: *)
Capacitor, Ceramic (MLCC), 100uF, ±20%, ±20%, SMD 0805; Manufacturer: Murata Electronics; Manufacturer Part Number: GRM21BC80E107ME15L
footprint CAP-0805 (0805 (2012M) Capacitor)
pins: 1, 2

## GRM21BC80G107ME15L
designator C?  Capacitance: 100uF  (hidden comment: *)
Capacitor, Ceramic (MLCC), 100uF, ±20%, 4V, X6S, ±20%, SMD 0805; Manufacturer: Murata Electronics; Manufacturer Part Number: GRM21BC80G107ME15L
footprint CAP-0805 (0805 (2012M) Capacitor)
pins: 1, 2

## GRM21BC80G476ME15L
designator C?  Capacitance: 47uF  (hidden comment: *)
Capacitor, Ceramic (MLCC), 47uF, ±20%, 4V, X6S, ±20%, SMD 0805; Manufacturer: Murata Electronics; Manufacturer Part Number: GRM21BC80G476ME15L
footprint CAP-0805 (0805 (2012M) Capacitor)
pins: 1, 2

## GRM21BC80J226ME51L
designator C?  Capacitance: 22uF  (hidden comment: *)
Capacitor, Ceramic (MLCC), 22uF, ±20%, 6.3V, X6S, ±20%, SMD 0805; Manufacturer: Murata Electronics; Manufacturer Part Number: GRM21BC80J226ME51L
footprint CAP-0805 (0805 (2012M) Capacitor)
pins: 1, 2

## GRM21BC81A226ME44L
designator C?  Capacitance: 22uF  (hidden comment: *)
Capacitor, Ceramic (MLCC), 22uF, ±20%, ±20%, SMD 0805; Manufacturer: Murata Electronics; Manufacturer Part Number: GRM21BC81A226ME44L
footprint CAP-0805 (0805 (2012M) Capacitor)
pins: 1, 2

## GRM21BC81C106KA73L
designator C?  Capacitance: 10uF  (hidden comment: *)
Capacitor, Ceramic (MLCC), 10uF, ±10%, 16V, X6S, ±10%, SMD 0805; Manufacturer: Murata Electronics; Manufacturer Part Number: GRM21BC81C106KA73L
footprint CAP-0805 (0805 (2012M) Capacitor)
pins: 1, 2

## GRM21BC81C226ME44L
designator C?  Capacitance: 22uF  (hidden comment: *)
Capacitor, Ceramic (MLCC), 22uF, ±20%, 16V, X6S, ±20%, SMD 0805; Manufacturer: Murata Electronics; Manufacturer Part Number: GRM21BC81C226ME44L
footprint CAP-0805 (0805 (2012M) Capacitor)
pins: 1, 2

## GRM21BC81E106KE51L
designator C?  Capacitance: 10uF  (hidden comment: *)
Capacitor, Ceramic (MLCC), 10uF, ±10%, 25V, X6S, ±10%, SMD 0805; Manufacturer: Murata Electronics; Manufacturer Part Number: GRM21BC81E106KE51L
footprint CAP-0805 (0805 (2012M) Capacitor)
pins: 1, 2

## GRM21BC81H475KE11L
designator C?  Capacitance: 4.7uF  (hidden comment: *)
Capacitor, Ceramic (MLCC), 4.7uF, ±10%, 50V, X6S, ±10%, SMD 0805; Manufacturer: Murata Electronics; Manufacturer Part Number: GRM21BC81H475KE11L
footprint CAP-0805 (0805 (2012M) Capacitor)
pins: 1, 2

## GRM21BD70J226ME44L
designator C?  Capacitance: 22uF  (hidden comment: *)
Capacitor, Ceramic (MLCC), 22uF, ±20%, 6.3V, ±20%, SMD 0805; Manufacturer: Murata Electronics; Manufacturer Part Number: GRM21BD70J226ME44L
footprint CAP-0805 (0805 (2012M) Capacitor)
pins: 1, 2

## GRM21BD71A226ME44L
designator C?  Capacitance: 22uF  (hidden comment: *)
Capacitor, Ceramic (MLCC), 22uF, ±20%, 10V, X7T, ±20%, SMD 0805; Manufacturer: Murata Electronics; Manufacturer Part Number: GRM21BD71A226ME44L
footprint CAP-0805 (0805 (2012M) Capacitor)
pins: 1, 2

## GRM21BD72A225KE01L
designator C?  Capacitance: 2.2uF  (hidden comment: *)
Capacitor, Ceramic (MLCC), 2.2uF, ±10%, 100V, X7T, ±10%, SMD 0805; Manufacturer: Murata Electronics; Manufacturer Part Number: GRM21BD72A225KE01L
footprint CAP-0805 (0805 (2012M) Capacitor)
pins: 1, 2

## GRM21BE70G226ME51L
designator C?  Capacitance: 22uF  (hidden comment: *)
Capacitor, Ceramic (MLCC), 22uF, ±20%, 4V, X7U, ±20%, SMD 0805; Manufacturer: Murata Electronics; Manufacturer Part Number: GRM21BE70G226ME51L
footprint CAP-0805 (0805 (2012M) Capacitor)
pins: 1, 2

## GRM21BR6YA106KE43L
designator C?  Capacitance: 10uF  (hidden comment: *)
Capacitor, Ceramic (MLCC), 10uF, ±10%, 35V, X5R, ±10%, SMD 0805; Manufacturer: Murata Electronics; Manufacturer Part Number: GRM21BR6YA106KE43L
footprint CAP-0805 (0805 (2012M) Capacitor)
pins: 1, 2

## GRM21BR6YA106ME43L
designator C?  Capacitance: 10uF  (hidden comment: *)
Capacitor, Ceramic (MLCC), 10uF, ±20%, 35V, X5R, ±20%, SMD 0805; Manufacturer: Murata Electronics; Manufacturer Part Number: GRM21BR6YA106ME43L
footprint CAP-0805 (0805 (2012M) Capacitor)
pins: 1, 2

## GRM21BR60G107ME11L
designator C?  Capacitance: 100uF  (hidden comment: *)
Capacitor, Ceramic (MLCC), 100uF, ±20%, ±20%, SMD 0805; Manufacturer: Murata Electronics; Manufacturer Part Number: GRM21BR60G107ME11L
footprint CAP-0805 (0805 (2012M) Capacitor)
pins: 1, 2

## GRM21BR60G107ME15L
designator C?  Capacitance: 100uF  (hidden comment: *)
Capacitor, Ceramic (MLCC), 100uF, ±20%, 4V, X5R, ±20%, SMD 0805; Manufacturer: Murata Electronics; Manufacturer Part Number: GRM21BR60G107ME15L
footprint CAP-0805 (0805 (2012M) Capacitor)
pins: 1, 2

## GRM21BR60J106KE19L
designator C?  Capacitance: 10uF  (hidden comment: *)
Capacitor, Ceramic (MLCC), 10uF, ±10%, 6.3V, X5R, ±10%, SMD 0805; Manufacturer: Murata Electronics; Manufacturer Part Number: GRM21BR60J106KE19L
footprint CAP-0805 (0805 (2012M) Capacitor)
pins: 1, 2

## GRM21BR60J107ME15L
designator C?  Capacitance: 100uF  (hidden comment: *)
Capacitor, Ceramic (MLCC), 100uF, ±20%, 6.3V, X5R, ±20%, SMD 0805; Manufacturer: Murata Electronics; Manufacturer Part Number: GRM21BR60J107ME15L
footprint CAP-0805 (0805 (2012M) Capacitor)
pins: 1, 2

## GRM21BR60J226ME39L
designator C?  Capacitance: 22uF  (hidden comment: *)
Capacitor, Ceramic (MLCC), 22uF, ±20%, 6.3V, X5R, ±20%, SMD 0805; Manufacturer: Murata Electronics; Manufacturer Part Number: GRM21BR60J226ME39L
footprint CAP-0805 (0805 (2012M) Capacitor)
pins: 1, 2

## GRM21BR60J335KA11L
designator C?  Capacitance: 3.3uF  (hidden comment: *)
Capacitor, Ceramic (MLCC), 3.3uF, ±10%, 6.3V, X5R, ±10%, SMD 0805; Manufacturer: Murata Electronics; Manufacturer Part Number: GRM21BR60J335KA11L
footprint CAP-0805 (0805 (2012M) Capacitor)
pins: 1, 2

## GRM21BR60J476ME01L
designator C?  Capacitance: 47uF  (hidden comment: *)
Capacitor, Ceramic (MLCC), 47uF, ±20%, 6.3V, X5R, ±20%, SMD 0805; Manufacturer: Murata Electronics; Manufacturer Part Number: GRM21BR60J476ME01L
footprint CAP-0805 (0805 (2012M) Capacitor)
pins: 1, 2

## GRM21BR60J476ME15L
designator C?  Capacitance: 47uF  (hidden comment: *)
Capacitor, Ceramic (MLCC), 47uF, ±20%, 6.3V, X5R, ±20%, SMD 0805; Manufacturer: Murata Electronics; Manufacturer Part Number: GRM21BR60J476ME15L
footprint CAP-0805 (0805 (2012M) Capacitor)
pins: 1, 2

## GRM21BR61A106KE19L
designator C?  Capacitance: 10uF  (hidden comment: *)
Capacitor, Ceramic (MLCC), 10uF, ±10%, 10V, X5R, ±10%, SMD 0805; Manufacturer: Murata Electronics; Manufacturer Part Number: GRM21BR61A106KE19L
footprint CAP-0805 (0805 (2012M) Capacitor)
pins: 1, 2

## GRM21BR61A226ME44L
designator C?  Capacitance: 22uF  (hidden comment: *)
Capacitor, Ceramic (MLCC), 22uF, ±20%, 10V, X5R, ±20%, SMD 0805; Manufacturer: Murata Electronics; Manufacturer Part Number: GRM21BR61A226ME44L
footprint CAP-0805 (0805 (2012M) Capacitor)
pins: 1, 2

## GRM21BR61A226ME51L
designator C?  Capacitance: 22uF  (hidden comment: *)
Capacitor, Ceramic (MLCC), 22uF, ±20%, 10V, X5R, ±20%, SMD 0805; Manufacturer: Murata Electronics; Manufacturer Part Number: GRM21BR61A226ME51L
footprint CAP-0805 (0805 (2012M) Capacitor)
pins: 1, 2

## GRM21BR61C106KE15K
designator C?  Capacitance: 10uF  (hidden comment: *)
Capacitor, Ceramic (MLCC), 10uF, ±10%, 16V, X5R, ±10%, SMD 0805; Manufacturer: Murata Electronics; Manufacturer Part Number: GRM21BR61C106KE15K
footprint CAP-0805 (0805 (2012M) Capacitor)
pins: 1, 2

## GRM21BR61C106KE15L
designator C?  Capacitance: 10uF  (hidden comment: *)
Capacitor, Ceramic (MLCC), 10uF, ±10%, 16V, X5R, ±10%, SMD 0805; Manufacturer: Murata Electronics; Manufacturer Part Number: GRM21BR61C106KE15L
footprint CAP-0805 (0805 (2012M) Capacitor)
pins: 1, 2

## GRM21BR61C475KA88L
designator C?  Capacitance: 4.7uF  (hidden comment: *)
Capacitor, Ceramic (MLCC), 4.7uF, ±10%, 16V, X5R, ±10%, SMD 0805; Manufacturer: Murata Electronics; Manufacturer Part Number: GRM21BR61C475KA88L
footprint CAP-0805 (0805 (2012M) Capacitor)
pins: 1, 2

## GRM21BR61E106KA73L
designator C?  Capacitance: 10uF  (hidden comment: *)
Capacitor, Ceramic (MLCC), 10uF, ±10%, 25V, X5R, ±10%, SMD 0805; Manufacturer: Murata Electronics; Manufacturer Part Number: GRM21BR61E106KA73L
footprint CAP-0805 (0805 (2012M) Capacitor)
pins: 1, 2

## GRM21BR61E106MA73L
designator C?  Capacitance: 10uF  (hidden comment: *)
Capacitor, Ceramic (MLCC), 10uF, ±20%, 25V, X5R, ±20%, SMD 0805; Manufacturer: Murata Electronics; Manufacturer Part Number: GRM21BR61E106MA73L
footprint CAP-0805 (0805 (2012M) Capacitor)
pins: 1, 2

## GRM21BR61E225KA12L
designator C?  Capacitance: 2.2uF  (hidden comment: *)
Capacitor, Ceramic (MLCC), 2.2uF, ±10%, 25V, X5R, ±10%, SMD 0805; Manufacturer: Murata Electronics; Manufacturer Part Number: GRM21BR61E225KA12L
footprint CAP-0805 (0805 (2012M) Capacitor)
pins: 1, 2

## GRM21BR61E226ME44L
designator C?  Capacitance: 22uF  (hidden comment: *)
Capacitor, Ceramic (MLCC), 22uF, ±20%, 25V, X5R, ±20%, SMD 0805; Manufacturer: Murata Electronics; Manufacturer Part Number: GRM21BR61E226ME44L
footprint CAP-0805 (0805 (2012M) Capacitor)
pins: 1, 2

## GRM21BR61E475KA12L
designator C?  Capacitance: 4.7uF  (hidden comment: *)
Capacitor, Ceramic (MLCC), 4.7uF, ±10%, 25V, X5R, ±10%, SMD 0805; Manufacturer: Murata Electronics; Manufacturer Part Number: GRM21BR61E475KA12L
footprint CAP-0805 (0805 (2012M) Capacitor)
pins: 1, 2

## GRM21BR61H225KA73L
designator C?  Capacitance: 2.2uF  (hidden comment: *)
Capacitor, Ceramic (MLCC), 2.2uF, ±10%, 50V, X5R, ±10%, SMD 0805; Manufacturer: Murata Electronics; Manufacturer Part Number: GRM21BR61H225KA73L
footprint CAP-0805 (0805 (2012M) Capacitor)
pins: 1, 2

## GRM21BR61H475KE51L
designator C?  Capacitance: 4.7uF  (hidden comment: *)
Capacitor, Ceramic (MLCC), 4.7uF, ±10%, 50V, X5R, ±10%, SMD 0805; Manufacturer: Murata Electronics; Manufacturer Part Number: GRM21BR61H475KE51L
footprint CAP-0805 (0805 (2012M) Capacitor)
pins: 1, 2

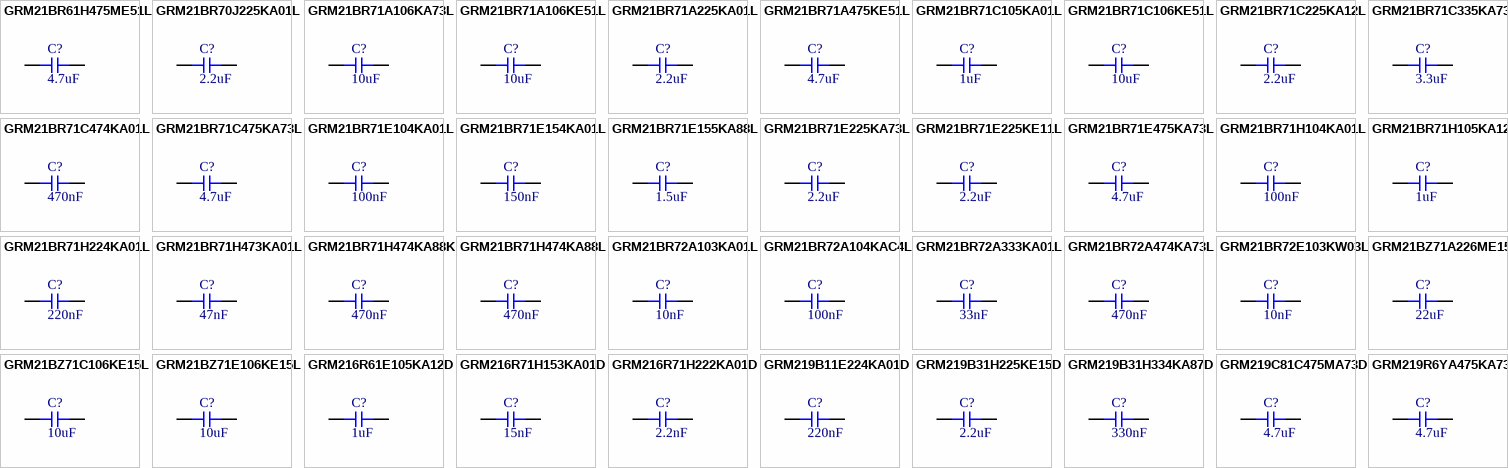
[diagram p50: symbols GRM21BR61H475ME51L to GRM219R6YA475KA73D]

## GRM21BR61H475ME51L
designator C?  Capacitance: 4.7uF  (hidden comment: *)
Capacitor, Ceramic (MLCC), 4.7uF, ±20%, 50V, X5R, ±20%, SMD 0805; Manufacturer: Murata Electronics; Manufacturer Part Number: GRM21BR61H475ME51L
footprint CAP-0805 (0805 (2012M) Capacitor)
pins: 1, 2

## GRM21BR70J225KA01L
designator C?  Capacitance: 2.2uF  (hidden comment: *)
Capacitor, Ceramic (MLCC), 2.2uF, ±10%, 6.3V, X7R, ±10%, SMD 0805; Manufacturer: Murata Electronics; Manufacturer Part Number: GRM21BR70J225KA01L
footprint CAP-0805 (0805 (2012M) Capacitor)
pins: 1, 2

## GRM21BR71A106KA73L
designator C?  Capacitance: 10uF  (hidden comment: *)
Capacitor, Ceramic (MLCC), 10uF, ±10%, 10V, X7R, ±10%, SMD 0805; Manufacturer: Murata Electronics; Manufacturer Part Number: GRM21BR71A106KA73L
footprint CAP-0805 (0805 (2012M) Capacitor)
pins: 1, 2

## GRM21BR71A106KE51L
designator C?  Capacitance: 10uF  (hidden comment: *)
Capacitor, Ceramic (MLCC), 10uF, ±10%, 10V, X7R, ±10%, SMD 0805; Manufacturer: Murata Electronics; Manufacturer Part Number: GRM21BR71A106KE51L
footprint CAP-0805 (0805 (2012M) Capacitor)
pins: 1, 2

## GRM21BR71A225KA01L
designator C?  Capacitance: 2.2uF  (hidden comment: *)
Capacitor, Ceramic (MLCC), 2.2uF, ±10%, 10V, X7R, ±10%, SMD 0805; Manufacturer: Murata Electronics; Manufacturer Part Number: GRM21BR71A225KA01L
footprint CAP-0805 (0805 (2012M) Capacitor)
pins: 1, 2

## GRM21BR71A475KE51L
designator C?  Capacitance: 4.7uF  (hidden comment: *)
Capacitor, Ceramic (MLCC), 4.7uF, ±10%, 10V, X7R, ±10%, SMD 0805; Manufacturer: Murata Electronics; Manufacturer Part Number: GRM21BR71A475KE51L
footprint CAP-0805 (0805 (2012M) Capacitor)
pins: 1, 2

## GRM21BR71C105KA01L
designator C?  Capacitance: 1uF  (hidden comment: *)
Capacitor, Ceramic (MLCC), 1uF, ±10%, 16V, X7R, ±10%, SMD 0805; Manufacturer: Murata Electronics; Manufacturer Part Number: GRM21BR71C105KA01L
footprint CAP-0805 (0805 (2012M) Capacitor)
pins: 1, 2

## GRM21BR71C106KE51L
designator C?  Capacitance: 10uF  (hidden comment: *)
Capacitor, Ceramic (MLCC), 10uF, ±10%, 16V, X7R, ±10%, SMD 0805; Manufacturer: Murata Electronics; Manufacturer Part Number: GRM21BR71C106KE51L
footprint CAP-0805 (0805 (2012M) Capacitor)
pins: 1, 2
